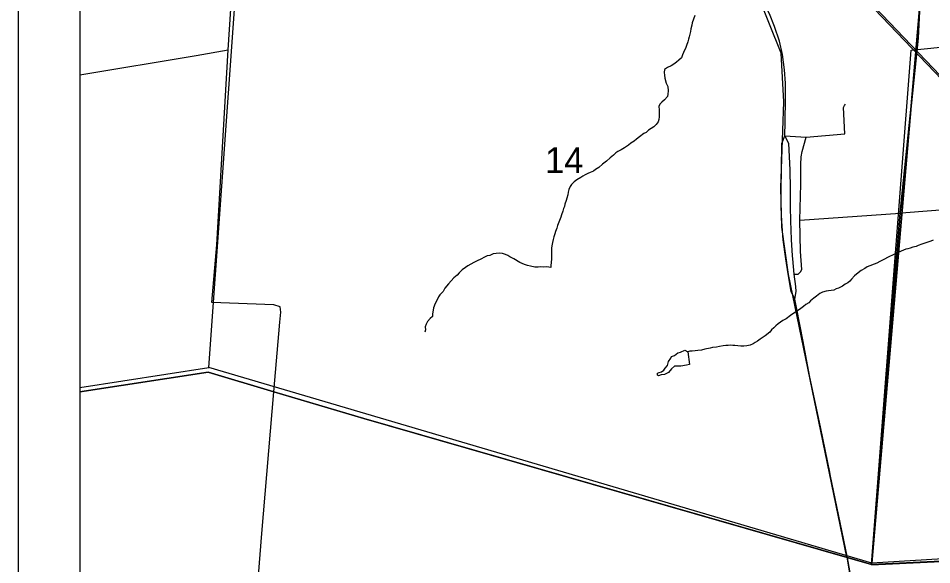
# Model space of a CAD drawing. Extents: x 0 to 34, y 0 to 22.
# Drawn here: x 2 to 3.482, y 15.362 to 16.249 of the extents above; entities that cross this region are included whole.
import ezdxf

# ---------------------------------------------------------------- set-up
doc = ezdxf.new("R2010")
doc.units = 0
for name, color, linetype in [('Default', 7, 'Continuous'), ('GM_X_City_Street', 7, 'Continuous'), ('GM_X_County_Road', 7, 'Continuous'), ('GM_X_Minor_River', 7, 'Continuous'), ('GM_X_Rail_Line', 7, 'Continuous'), ('GM_X_Section', 7, 'Continuous'), ('GM_X_Section_Text', 7, 'Continuous'), ('GM_X_State_Route', 7, 'Continuous'), ('GM_X_Township_Road', 7, 'Continuous'), ('SH_Cut_Line', 7, 'Continuous'), ('SH_Data', 7, 'Continuous')]:
    doc.layers.add(name, color=color, linetype=linetype)

msp = doc.modelspace()

# ---------------------------------------------------------------- linework, layer by layer
at = {"layer": 'Default'}
msp.add_lwpolyline([(2.8131, 18.5849), (2.7778, 18.1558), (2.5327, 18.2417), (2.4945, 17.7428), (2.4362, 17.7466), (2.1, 17.6674), (2.1, 15.6423), (2.3082, 15.6745), (2.5606, 15.599), (3.3845, 15.362), (3.4491, 16.1969), (3.7972, 16.2327), (3.8103, 16.3888), (3.7967, 16.3876), (3.8259, 16.7634), (3.5062, 16.7356), (3.5564, 17.3695), (3.6226, 18.1301), (3.6176, 18.1479), (3.628, 18.1636), (3.6366, 18.1888), (3.6479, 18.2377)], dxfattribs=at)
msp.add_lwpolyline([(2.1, 16.6619), (2.1, 15.6496), (2.3094, 15.6817), (2.3835, 16.7168)], close=True, dxfattribs=at)
at = {"layer": 'GM_X_City_Street'}
for points in [[(2.4148, 15.6422), (2.4247, 15.7554), (2.4262, 15.7717), (2.4248, 15.7805), (2.415, 15.7837), (2.3139, 15.7875), (2.3225, 15.8811), (2.3405, 16.1978)], [(3.2441, 16.0578), (3.2789, 16.0561), (3.3412, 16.0612), (3.3392, 16.1042), (3.3407, 16.1075), (3.3427, 16.1094)], [(3.2593, 15.8334), (3.2655, 15.8337), (3.2696, 15.837), (3.2714, 15.841), (3.2696, 15.8703), (3.2682, 15.9214), (3.2699, 15.9798), (3.27, 16.0117), (3.2707, 16.0238), (3.2719, 16.0324), (3.2789, 16.0561)], [(2.3819, 15.2419), (2.3955, 15.4127), (2.4148, 15.6422)]]:
    msp.add_lwpolyline(points, dxfattribs=at)
at = {"layer": 'GM_X_County_Road'}
for points in [[(2.3405, 16.1978), (2.3517, 16.363), (2.3564, 16.4238), (2.3586, 16.4526), (2.364, 16.5124), (2.3782, 16.6756), (2.379, 16.6904), (2.3787, 16.6974), (2.377, 16.7065), (2.3753, 16.7133), (2.3735, 16.7168), (2.3707, 16.7224), (2.3664, 16.7287), (2.3641, 16.7319)], [(3.3848, 15.3615), (3.4978, 15.3669), (3.9249, 15.3983), (4.4077, 15.4283)]]:
    msp.add_lwpolyline(points, dxfattribs=at)
at = {"layer": 'GM_X_Minor_River'}
for points in [[(3.0979, 16.2534), (3.0958, 16.2474), (3.0937, 16.2417)], [(3.0937, 16.2417), (3.0929, 16.2376), (3.0915, 16.2315), (3.0907, 16.2274), (3.0898, 16.2232), (3.0889, 16.2187), (3.0876, 16.2149), (3.0864, 16.2108), (3.0843, 16.2048), (3.0831, 16.2014), (3.0798, 16.1931), (3.0782, 16.1897), (3.0761, 16.1849), (3.0722, 16.1808), (3.0683, 16.1775), (3.064, 16.1742), (3.0594, 16.1717), (3.0536, 16.1688), (3.0489, 16.1655), (3.0484, 16.1606), (3.0487, 16.1564), (3.0493, 16.1518), (3.0513, 16.1434), (3.0539, 16.1384), (3.0548, 16.1311), (3.0543, 16.1258), (3.0534, 16.1217), (3.0487, 16.1165), (3.0444, 16.1125), (3.0409, 16.1095), (3.0396, 16.1058), (3.0402, 16.1), (3.04, 16.0936), (3.0403, 16.089), (3.0397, 16.0845), (3.0385, 16.0807), (3.035, 16.0766), (3.0314, 16.0729), (3.0229, 16.0671), (3.019, 16.0634), (3.0151, 16.0616), (3.0081, 16.0565), (3.0031, 16.0525), (2.9996, 16.0496), (2.9942, 16.0463), (2.9903, 16.043), (2.9837, 16.0386), (2.9783, 16.0354), (2.9732, 16.0325), (2.9698, 16.0307), (2.9658, 16.0266), (2.9604, 16.0223), (2.9545, 16.0167), (2.9483, 16.012), (2.9421, 16.0065), (2.937, 16.0032), (2.9335, 16.0006), (2.9282, 15.9985), (2.9243, 15.9967), (2.9201, 15.9946), (2.9162, 15.9924), (2.9127, 15.9906), (2.9065, 15.9866), (2.9023, 15.9833), (2.898, 15.9793), (2.8956, 15.9759), (2.8935, 15.9707), (2.8926, 15.9665), (2.8917, 15.962), (2.8901, 15.9567), (2.8892, 15.9533), (2.8871, 15.9473), (2.8863, 15.9435), (2.885, 15.9401), (2.8838, 15.936), (2.8817, 15.93), (2.8804, 15.9258), (2.8775, 15.9179), (2.8751, 15.9127), (2.8738, 15.9082), (2.8718, 15.9029), (2.8705, 15.8988), (2.8689, 15.8939), (2.868, 15.8897), (2.8671, 15.8848), (2.8658, 15.8795), (2.8653, 15.8757), (2.8656, 15.8723), (2.8652, 15.8586), (2.8646, 15.8526), (2.8641, 15.8476), (2.8644, 15.8442), (2.8576, 15.8452), (2.8519, 15.845), (2.8477, 15.8455), (2.8435, 15.8448), (2.8382, 15.845), (2.831, 15.8464), (2.8265, 15.8477), (2.8216, 15.8489), (2.8137, 15.8526)], [(3.4848, 15.8887), (3.481, 15.8873), (3.476, 15.8856), (3.4698, 15.8831), (3.4664, 15.8821), (3.4606, 15.88), (3.4572, 15.8786), (3.4518, 15.8772), (3.4472, 15.8758), (3.4438, 15.8748), (3.4403, 15.8738), (3.4365, 15.8724), (3.428, 15.8688), (3.4211, 15.8656), (3.4118, 15.8609), (3.4049, 15.8574), (3.3983, 15.8538), (3.3933, 15.8516), (3.389, 15.8495), (3.3818, 15.847), (3.3775, 15.8453), (3.3736, 15.8427), (3.3678, 15.8395), (3.3632, 15.8358)], [(2.8137, 15.8526), (2.804, 15.8582), (2.7976, 15.8618), (2.7943, 15.8638), (2.7905, 15.8655), (2.786, 15.8668), (2.7807, 15.8673), (2.7757, 15.8671), (2.7708, 15.8665), (2.7654, 15.864), (2.7612, 15.863), (2.7558, 15.8605), (2.7515, 15.8583), (2.7438, 15.8547), (2.7392, 15.8522), (2.7342, 15.8497), (2.7295, 15.8468), (2.7256, 15.8443), (2.7206, 15.8406), (2.7155, 15.8358), (2.712, 15.8321), (2.7069, 15.8274), (2.7026, 15.8229), (2.6983, 15.8177), (2.6924, 15.8107), (2.6895, 15.8051), (2.6844, 15.7999), (2.6821, 15.7966), (2.6796, 15.7917), (2.6764, 15.7861), (2.6739, 15.7786), (2.6731, 15.7748), (2.6725, 15.7691), (2.672, 15.7649), (2.6685, 15.7616), (2.6642, 15.7564), (2.6618, 15.7523), (2.6605, 15.7478), (2.6607, 15.7432), (2.6599, 15.7394)], [(3.3632, 15.8358), (3.3573, 15.8307), (3.3522, 15.8255), (3.3495, 15.8222), (3.346, 15.8196), (3.3421, 15.8171), (3.3375, 15.8142), (3.3313, 15.8109), (3.3274, 15.8095), (3.3236, 15.8077), (3.3194, 15.8067), (3.3148, 15.8065), (3.311, 15.8058), (3.3049, 15.8041), (3.301, 15.802), (3.2952, 15.7976), (3.2909, 15.7943), (3.2858, 15.7903), (3.2831, 15.7869), (3.2781, 15.784), (3.2742, 15.7811), (3.2699, 15.7778), (3.266, 15.7753), (3.2586, 15.7702), (3.2532, 15.7666), (3.2462, 15.7607), (3.2408, 15.7582), (3.2369, 15.7556), (3.2334, 15.7527), (3.2295, 15.7498), (3.226, 15.7465), (3.2225, 15.7432), (3.2194, 15.7395), (3.2123, 15.7336), (3.2089, 15.731), (3.2042, 15.7277), (3.1999, 15.7248), (3.1961, 15.7223), (3.1926, 15.7205), (3.1876, 15.7184), (3.1826, 15.717), (3.1773, 15.7168), (3.1727, 15.7165), (3.1629, 15.7176), (3.1594, 15.7177), (3.1556, 15.7182), (3.1522, 15.7179), (3.1484, 15.7177), (3.1438, 15.717), (3.1381, 15.7161), (3.1331, 15.7151), (3.1266, 15.7142), (3.1228, 15.7131), (3.1144, 15.7119), (3.1087, 15.7101), (3.1026, 15.7096), (3.0987, 15.7089), (3.0934, 15.7083), (3.0896, 15.7084), (3.0865, 15.7076)], [(3.0865, 15.7076), (3.0892, 15.6869), (3.0842, 15.6855), (3.075, 15.6842), (3.0716, 15.6843), (3.0652, 15.6841), (3.0601, 15.6797), (3.055, 15.6741), (3.0489, 15.6708), (3.0432, 15.6699), (3.0389, 15.6684), (3.0375, 15.6696), (3.0375, 15.6727), (3.0402, 15.6737), (3.044, 15.6748), (3.0475, 15.6777), (3.0499, 15.6811), (3.0534, 15.6852), (3.0551, 15.6916)], [(3.0551, 15.6916), (3.059, 15.6972), (3.0602, 15.6998), (3.0652, 15.7016), (3.0679, 15.7038), (3.0706, 15.706), (3.0745, 15.7071), (3.0818, 15.7103), (3.0865, 15.7076)]]:
    msp.add_lwpolyline(points, dxfattribs=at)
at = {"layer": 'GM_X_Rail_Line'}
for points in [[(4.2039, 15.4164), (3.7439, 15.8967), (3.3428, 16.3169), (3.153, 16.5162), (2.8982, 16.7851), (2.7005, 16.9902), (2.596, 17.1019), (2.4324, 17.2718), (2.1, 17.6214)], [(4.2011, 15.4158), (3.7421, 15.895), (3.341, 16.3152), (3.1512, 16.5145), (2.8964, 16.7834), (2.6987, 16.9885), (2.5942, 17.1001), (2.4306, 17.27), (2.1, 17.6178)], [(3.3444, 15.3738), (3.2499, 15.8327), (3.2392, 15.9096), (3.2376, 15.9737), (3.2425, 16.1133), (3.238, 16.192), (3.2014, 16.2841), (3.1437, 16.3394), (3.0323, 16.4123), (2.5886, 16.6952), (2.4488, 16.7831), (2.3738, 16.8381), (2.1, 17.0501)], [(3.3444, 15.3738), (3.363, 15.2647), (3.3684, 15.204), (3.3673, 15.1436), (3.3329, 14.7516), (3.3187, 14.6921), (3.2982, 14.6255), (3.2913, 14.593), (3.292, 14.5555), (3.2969, 14.5231), (3.3153, 14.4703), (3.3316, 14.4294), (3.3333, 14.3984), (3.3271, 14.3547), (3.3051, 14.1)]]:
    msp.add_lwpolyline(points, dxfattribs=at)
at = {"layer": 'GM_X_Section'}
for points in [[(2.3835, 16.7168), (3.4704, 16.3589), (3.385, 15.3645), (2.3094, 15.6817)], [(4.4981, 16.447), (4.4056, 15.4266), (3.385, 15.3645), (3.4704, 16.3589)]]:
    msp.add_lwpolyline(points, close=True, dxfattribs=at)
at = {"layer": 'GM_X_State_Route'}
msp.add_line((3.2504, 16.0458), (3.2441, 16.0578), dxfattribs=at)
for points in [[(3.2441, 16.0578), (3.2444, 16.0801), (3.245, 16.1185), (3.2451, 16.1435), (3.2437, 16.165), (3.2404, 16.1903), (3.2351, 16.2119), (3.2272, 16.2356), (3.2189, 16.2561), (3.209, 16.2746), (3.198, 16.2919), (3.1872, 16.3055), (3.1753, 16.3186), (3.1465, 16.3454)], [(3.2605, 15.7928), (3.2543, 15.8053), (3.2492, 15.8342), (3.2455, 15.8583), (3.2415, 15.8892), (3.2392, 15.9191), (3.2383, 15.9425), (3.2381, 15.9722), (3.2385, 16.0029), (3.2392, 16.0457), (3.2441, 16.0578)], [(3.2564, 15.8634), (3.2546, 15.8895), (3.2535, 15.9198), (3.2531, 15.943), (3.253, 15.9722), (3.2528, 16.0028), (3.2504, 16.0458)], [(3.2617, 15.8132), (3.2593, 15.8334), (3.2568, 15.8584), (3.2564, 15.8634)], [(3.2605, 15.7928), (3.2626, 15.8051), (3.2617, 15.8132)], [(3.3168, 15.5122), (3.3023, 15.5828), (3.2843, 15.6691), (3.2737, 15.724), (3.263, 15.7795), (3.2605, 15.7928)], [(3.3457, 15.3727), (3.3338, 15.4304), (3.3176, 15.5082), (3.3168, 15.5122)], [(3.3643, 15.2681), (3.3612, 15.2869), (3.3494, 15.352), (3.3457, 15.3727)]]:
    msp.add_lwpolyline(points, dxfattribs=at)
at = {"layer": 'GM_X_Township_Road'}
msp.add_line((3.4404, 15.9334), (3.5917, 15.9453), dxfattribs=at)
for points in [[(2.1, 18.801), (2.1, 15.6427), (2.3082, 15.6745), (2.4145, 15.6427), (2.5606, 15.599), (3.3455, 15.3733), (3.3845, 15.362), (3.4311, 15.9332), (3.4604, 16.2167), (3.4676, 16.3592), (3.5285, 17.1302), (3.548, 17.3706), (3.5984, 17.9897), (3.6087, 18.1157), (3.6104, 18.137), (3.6645, 18.801)], [(3.5285, 17.1302), (3.4676, 16.3592), (3.4604, 16.2167), (3.4311, 15.9332), (3.3845, 15.362), (3.4976, 15.3675)], [(2.1, 16.1573), (2.2887, 16.1885), (2.3405, 16.1978)], [(3.2682, 15.9214), (3.3383, 15.9258), (3.4313, 15.9327), (3.4404, 15.9334)], [(3.4976, 15.3675), (3.3845, 15.362), (3.3455, 15.3733), (2.5606, 15.599), (2.4145, 15.6427), (2.3082, 15.6745), (2.1, 15.6427), (2.1, 14.1), (5.2869, 14.1)]]:
    msp.add_lwpolyline(points, dxfattribs=at)
at = {"layer": 'SH_Cut_Line'}
for points in [[(2.1, 18.801), (2.1, 15.6427), (2.3082, 15.6745), (2.4145, 15.6427), (2.5606, 15.599), (3.3455, 15.3733), (3.3845, 15.362), (3.4976, 15.3675)], [(3.4976, 15.3675), (3.3845, 15.362), (3.3455, 15.3733), (2.5606, 15.599), (2.4145, 15.6427), (2.3082, 15.6745), (2.1, 15.6427), (2.1, 14.1), (8.9, 14.1)]]:
    msp.add_lwpolyline(points, dxfattribs=at)
at = {"layer": 'SH_Data'}
for p, q in [((2, 21), (2, 14)), ((2.1, 20.9), (2.1, 14.1))]:
    msp.add_line(p, q, dxfattribs=at)

# ---------------------------------------------------------------- texts
at = {"layer": 'GM_X_Section_Text'}
msp.add_text('14', height=0.04186, rotation=0, dxfattribs=at).set_placement((2.855, 15.9976))

doc.saveas('drawing.dxf')
